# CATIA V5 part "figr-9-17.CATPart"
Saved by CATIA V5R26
Part number: Part1
Bounding box of the stored display mesh (mm): x -77.304 to 77.304, y -77.304 to 125.507, z 0 to 125
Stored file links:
  D:\_Deepak\CATIA\CATIA V5-6R2016_Deepak\Resources\Part files\Partfiles\c09_catia_v5_6r2016_prt\figr-9-17.CATPart
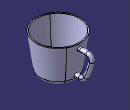
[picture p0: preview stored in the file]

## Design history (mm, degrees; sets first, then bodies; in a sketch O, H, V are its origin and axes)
Set1
  Plane1: type Normal, Curve Sketch3, RefPoint vertex of Sketch3
Body1 (main body)
  Sketch1 on yz-plane, origin (0, 0, 0), H (0, 1, 0), V (0, 0, 1)
    line L1 (0, 0) -> (60, 0)
    point P1 (60, 0)
    point P2 (60, 0)
    line L2 (60, 0) -> (77.5, 125)
    point P3 (77.5, 125)
    line L3 (77.5, 125) -> (0, 125)
    point P4 (0, 125)
    line L4 (0, 125) -> (0, 0)
    axis line L5 (0, 150.2858) -> (0, -31.0593)
    point P5 (0, 150.2858)
    radius about axis P1 L5 = 60
    radius about axis P3 L5 = 77.5
    distance L3 L1 = 125
    horizontal: L1 H, L3 H
    coincidence: P4 V, P2 P1, P5 V
    vertical: L4 V, L5 V
  Shaft1: profile Sketch1, axis Sketch1.L5, angle 360
  Fillet1: radius 15, on edge [face of Shaft1 | face of Shaft1]
  Shell1: ExtOffset 0, Face face of Shaft1, IntOffset 4
  Sketch2 on Plane1, origin (0, 62.9841, 0), H (-1, 0, 0), V (0, 0, 1)
    circle A1 centre (0, 22.002) radius 7.5
    reference projected point E1 (0, 22.002) from vertex of Sketch3
    radius A1 = 7.5
    concentricity: A1 E1
  Sketch3 on yz-plane, origin (0, 0, 0), H (0, 1, 0), V (0, 0, 1)
    line L1 (62.9841, 22.002) -> (78.2172, 22.002)
    arc A1 centre (78.2172, 44.1133) radius 22.1113 from (78.2172, 22.002) to (97.9307, 34.0988) ccw
    arc A2 centre (-112.3295, 140.9107) radius 235.8349 from (97.9307, 34.0988) to (117.8681, 89.6549) ccw
    arc A3 centre (104.0328, 92.7355) radius 14.1742 from (117.8681, 89.6549) to (104.4272, 106.9041) ccw
    arc A4 centre (93.6744, -279.4123) radius 386.4661 from (104.4272, 106.9041) to (82.9216, 106.9041) ccw
    horizontal: L1 H
    tangency: A1 L1, A2 A1, A3 A2, A4 A3
  Rib1: profile Sketch2, centre curve Sketch3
